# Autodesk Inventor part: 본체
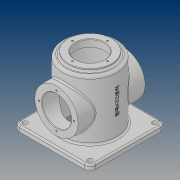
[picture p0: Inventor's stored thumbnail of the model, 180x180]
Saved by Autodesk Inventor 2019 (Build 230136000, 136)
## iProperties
Created: 2019-03
Part Number: 본체
Material: 일반
Document SubType Name: Modeling
Designer: PC312-16
Density: 1 g/cm^3
Appearance: 기본값
Author: PC312-16
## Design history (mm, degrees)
sketch "스케치1"
  geometry: L1 (0, 0)-(110, 0); L2 (102, 0)-(102, -40); L3 (102, -40)-(0, -40); L4 (0, -50)-(110, -50); L5 (110, -50)-(110, 0); L6 (0, -40)-(0, -50)
  constraints: 13 end point, 3 horizontal, 3 vertical, 2 point on line
  dimensions: "d0" = 110 distance of L1.start L1.end; "d1" = 100 diameter of L4 L1; "d3" = 80 diameter of L3 L1; "d4" = 8 distance of L1.end L2.start
revolve "회전1" sketch "스케치1" stored, may be unused: angle "d5" = 90 deg
sketch "스케치2"
  geometry: C1 r 40 at (0, 0); 1 further point
  constraints: 1 centre point, 1 coincident
  dimensions: "d6" = 80 diameter of C1
extrude "돌출1" join sketch "스케치2" distance "d7" = 5; taper "d8" = 0 deg
sketch "스케치3"
  geometry: C1 r 27 at (0, 0); 1 further point
  constraints: 1 centre point, 1 coincident
  dimensions: "d9" = 54 diameter of C1
extrude "돌출2" cut sketch "스케치3" distance "d10" = 13; taper "d11" = 0 deg
sketch "스케치4"
  geometry: L1 (70, 70)-(-70, 70); L2 (-70, 70)-(-70, -70); L3 (-70, -70)-(70, -70); L4 (70, -70)-(70, 70); L5 (70, 70)-(-70, -70); L6 (-70, 70)-(70, -70); C1 r 50 at (0, 0) reference; C2 r 50 at (0, 0) reference; C3 r 40 at (0, 0) reference; 1 further point
  constraints: 12 end point, 2 midpoint, 2 parallel, 1 horizontal, 1 perpendicular
  dimensions: "d12" = 140 distance of L3.end L2.end; "d13" = 140 distance of L2.end L1.end
extrude "돌출4" join sketch "스케치4" distance "d16" = 10; taper "d17" = 0 deg
node "작업 평면1"
sketch "스케치5"
  geometry: L1 (70, -10)-(-70, -10) reference; C1 r 40 at (0, 50); 2 further points
  constraints: 1 centre point, 1 midpoint, 1 vertical alignment
  dimensions: "d19" = 80 diameter of C1; "d20" = 60 distance from line of L1 C1.centre
extrude "돌출5" join sketch "스케치5" stored distance "d21" = 10; taper "d22" = 0 deg
fillet "모깎기1" dims "d23" = 3
sketch "스케치6"
  geometry: C1 r 40 at (0, 0) reference; 2 further points
  constraints: 1 vertical alignment
  dimensions: "d24" = 32.5 distance of C1.centre point (0, 32.5)
hole "구멍1" sketch "스케치6" at (0, 32.5) diameter "d25" = 3.242; stored, may be unused: countersink angle "d29" = 90 deg, drill point angle "d31" = 118 deg; dims "d26" = 8, "d27" = 4, "d28" = 2, "d30" = 10
sketch "스케치7"
  geometry: C1 r 40 at (0, 0) reference; C2 r 27 at (0, 0); 1 further point
  constraints: 1 centre point, 1 coincident
  dimensions: "d35" = 54 diameter of C2
extrude "돌출6" cut sketch "스케치7" extent not by distance; stored distance "d36" = 0; taper "d37" = 0 deg
sketch "스케치8"
  geometry: 2 further points
  constraints: 1 vertical alignment
  dimensions: "d38" = 32.5 distance of point (0, 0) point (0, 32.5)
hole "구멍2" sketch "스케치8" at (0, 32.5) diameter "d39" = 3.242; stored, may be unused: countersink angle "d43" = 90 deg, drill point angle "d45" = 118 deg; dims "d40" = 8, "d41" = 4, "d42" = 2, "d44" = 10
fillet "모깎기2" dims "d49" = 10
sketch "스케치9"
  geometry: C1 r 4.5 at (60, 60); A1 r 10 centre (60, 60) between (70, 60) and (60, 70) reference; 1 further point
  constraints: 1 centre point, 1 coincident
  dimensions: "d50" = 9 diameter of C1
extrude "돌출7" cut sketch "스케치9" extent not by distance; stored distance "d51" = 10; taper "d52" = 0 deg
fillet "모깎기3" dims "d59" = 5
fillet "모깎기4" dims "d60" = 3
fillet "모깎기5" dims "d61" = 3
chamfer "모따기1" distance "d62" = 1; stored, may be unused: second distance "d63" = 2, angle "d64" = 45 deg
fillet "모깎기6" dims "d65" = 3
node "작업 평면2"
sketch "스케치10"
  geometry: L1 (-10, -60)-(-10, 60) reference; 2 further points
  constraints: 1 horizontal alignment, 1 other
  dimensions: "d68" = 70 distance from line of L1 point (60, 0)
feature "엠보싱1" sketch "스케치10" dims "d69" = 0.5, "d70" = 0
node "솔리드1"
pattern_circular "원형 패턴1" dims angle "d33" = 360 deg
mirror "미러1"
pattern_circular "원형 패턴2" dims angle "d47" = 360 deg
pattern_linear "직사각형 패턴1" dims "d55" = 120, "d58" = 120
node "투영된 루프1"
other parameters: "d18" = 62
